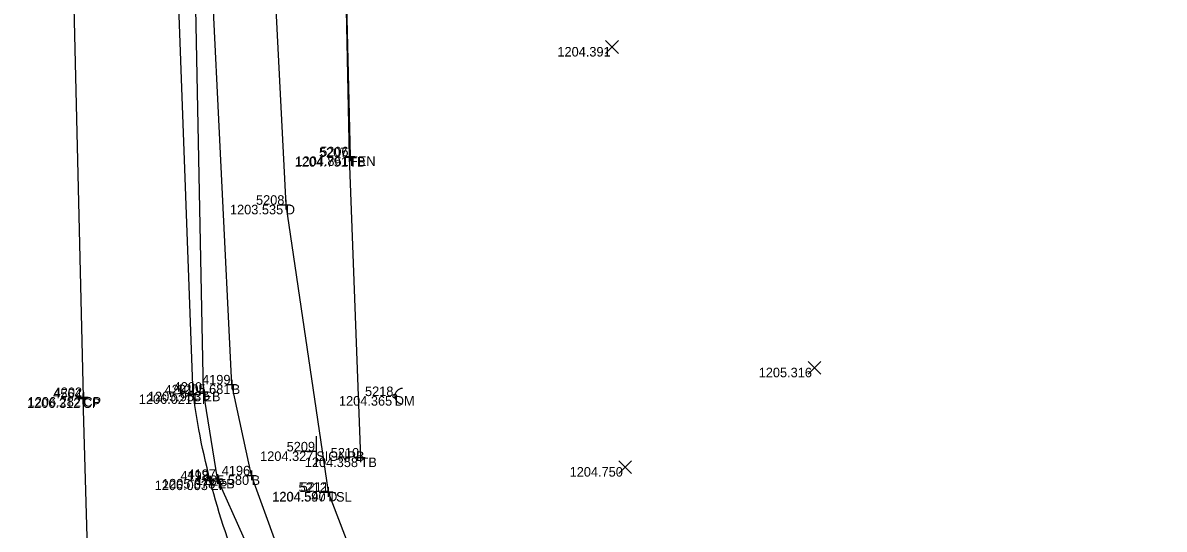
# Model space of a CAD drawing. Extents: x 2044996 to 2050343, y 455232 to 458054.
# Drawn here: x 2047624.3 to 2047743.9, y 457018.9 to 457071.9 of the extents above; entities that cross this region are included whole.
import ezdxf

# ---------------------------------------------------------------- set-up
doc = ezdxf.new("R2010")
doc.units = 0
for name, color, linetype in [('DR_X_Ditch', 7, 'Continuous'), ('DT_X_Contour_Minor', 7, 'Continuous'), ('DT_X_Contour_Text', 7, 'Continuous'), ('DT_X_Island', 7, 'Continuous'), ('DT_X_Spot_Elev', 7, 'Continuous'), ('DT_X_Triangles', 7, 'Continuous'), ('DT_X_Void', 7, 'Continuous'), ('PV_X_COP', 7, 'Continuous'), ('PV_X_EOP', 7, 'Continuous'), ('PV_X_Shoulder_Aggregate', 7, 'Continuous'), ('RD_X_Fence', 7, 'Continuous'), ('SN_X_Public', 7, 'Continuous'), ('SV_X_Break_Lines', 7, 'Continuous'), ('SV_X_Toe_of_Slope', 7, 'Continuous'), ('SV_X_Top_of_Bank', 7, 'Continuous')]:
    doc.layers.add(name, color=color, linetype=linetype)

msp = doc.modelspace()

# ---------------------------------------------------------------- linework, layer by layer
at = {"layer": 'DR_X_Ditch'}
msp.add_lwpolyline([(2047635.93, 457828.45), (2047636.46, 457778.33), (2047635.67, 457731.58), (2047635.87, 457688.92), (2047636.59, 457650.58), (2047637.14, 457615.31), (2047638.36, 457574.87), (2047638.82, 457526.07), (2047639.21, 457482.92), (2047639.9, 457443.66), (2047641.24, 457398.66), (2047642.28, 457344.51), (2047644.03, 457300.89), (2047646.18, 457262.24), (2047646.96, 457237.04), (2047650.76, 457191.22), (2047650.42, 457143.89), (2047649.26, 457104.81), (2047651.9, 457052.9), (2047656.34, 457022.85)], dxfattribs=at)
at = {"layer": 'DT_X_Island'}
msp.add_circle((2047663.32, 457032.87), 0.2, dxfattribs=at)
msp.add_arc((2047664.12, 457032.87), 0.8, 90, 270, dxfattribs=at)
at = {"layer": 'DT_X_Spot_Elev'}
for p, q in [((2047685.41, 457068.75), (2047686.75, 457070.09)), ((2047685.41, 457070.09), (2047686.75, 457068.75)), ((2047706.63, 457035.17), (2047707.96, 457036.5)), ((2047706.63, 457036.5), (2047707.96, 457035.17)), ((2047686.81, 457024.77), (2047688.14, 457026.1)), ((2047686.81, 457026.1), (2047688.14, 457024.77))]:
    msp.add_line(p, q, dxfattribs=at)
at = {"layer": 'DT_X_Void'}
for p, q in [((2047658.54, 457058.39), (2047658.54, 457057.39)), ((2047658.63, 457058.47), (2047658.63, 457057.47)), ((2047658.04, 457057.89), (2047659.04, 457057.89)), ((2047658.13, 457057.97), (2047659.13, 457057.97)), ((2047658.54, 457057.89), (2047658.54, 457057.89)), ((2047658.63, 457057.97), (2047658.63, 457057.97)), ((2047651.9, 457053.4), (2047651.9, 457052.4)), ((2047651.4, 457052.9), (2047652.4, 457052.9)), ((2047651.9, 457052.9), (2047651.9, 457052.9)), ((2047645.73, 457034.09), (2047646.73, 457034.09)), ((2047646.23, 457034.59), (2047646.23, 457033.59)), ((2047646.23, 457034.09), (2047646.23, 457034.09)), ((2047630.62, 457033.13), (2047630.62, 457032.13)), ((2047630.7, 457033.27), (2047630.7, 457032.27)), ((2047641.71, 457033.05), (2047642.71, 457033.05)), ((2047642.21, 457033.55), (2047642.21, 457032.55)), ((2047642.21, 457033.05), (2047642.21, 457033.05)), ((2047642.77, 457033.33), (2047643.77, 457033.33)), ((2047643.27, 457033.83), (2047643.27, 457032.83)), ((2047643.27, 457033.33), (2047643.27, 457033.33)), ((2047630.12, 457032.63), (2047631.12, 457032.63)), ((2047630.2, 457032.77), (2047631.2, 457032.77)), ((2047630.62, 457032.63), (2047630.62, 457032.63)), ((2047630.7, 457032.77), (2047630.7, 457032.77)), ((2047659.73, 457026.94), (2047659.73, 457025.94)), ((2047659.23, 457026.44), (2047660.23, 457026.44)), ((2047659.73, 457026.44), (2047659.73, 457026.44)), ((2047643.98, 457024.53), (2047643.98, 457023.53)), ((2047644.76, 457024.7), (2047644.76, 457023.7)), ((2047647.81, 457024.57), (2047648.81, 457024.57)), ((2047648.31, 457025.07), (2047648.31, 457024.07)), ((2047648.31, 457024.57), (2047648.31, 457024.57)), ((2047643.48, 457024.03), (2047644.48, 457024.03)), ((2047643.98, 457024.03), (2047643.98, 457024.03)), ((2047644.26, 457024.2), (2047645.26, 457024.2)), ((2047644.76, 457024.2), (2047644.76, 457024.2)), ((2047656.34, 457023.35), (2047656.34, 457022.35)), ((2047656.35, 457023.33), (2047656.35, 457022.33)), ((2047655.84, 457022.85), (2047656.84, 457022.85)), ((2047655.85, 457022.83), (2047656.85, 457022.83)), ((2047656.34, 457022.85), (2047656.34, 457022.85)), ((2047656.35, 457022.83), (2047656.35, 457022.83))]:
    msp.add_line(p, q, dxfattribs=at)
at = {"layer": 'PV_X_COP'}
for points in [[(2047630.7, 457032.77), (2047629.57, 457079.46), (2047628.83, 457121.31), (2047627.83, 457168.37), (2047627.23, 457213.89), (2047626.35, 457261.41), (2047625.27, 457313.88), (2047624.14, 457367.69), (2047623.14, 457414.96), (2047622.16, 457463.48), (2047621.21, 457510.6), (2047620.34, 457561.9), (2047619.47, 457614.83), (2047618.33, 457662.23), (2047617.51, 457713.13), (2047616.39, 457759.38), (2047615.44, 457807.27), (2047614.41, 457854.52), (2047614.29, 457881.56), (2047613.16, 457931.14), (2047612.06, 457984.05), (2047611.48, 458032.26), (2047610.91, 458052.26)], [(2047630.62, 457032.63), (2047631.64, 456997.55), (2047632.38, 456961.54), (2047632.83, 456926.92), (2047633.49, 456905.89), (2047634.02, 456875.59), (2047634.74, 456845.71), (2047636.01, 456795.7), (2047636.79, 456753.22), (2047638.14, 456705.84), (2047638.65, 456684.97), (2047639.72, 456638.63)]]:
    msp.add_lwpolyline(points, dxfattribs=at)
at = {"layer": 'PV_X_EOP'}
msp.add_line((2047642.21, 457033.05), (2047640.51, 457078.62), dxfattribs=at)
msp.add_open_spline([(2047683.07, 456986.61), (2047675.94, 456988.74), (2047666.02, 456993.59), (2047654.88, 457002.74), (2047647.77, 457012.14), (2047644.12, 457022.51), (2047642.59, 457029.98), (2047642.21, 457033.05)], degree=3, dxfattribs=at)
at = {"layer": 'PV_X_Shoulder_Aggregate'}
msp.add_lwpolyline([(2047765.41, 456957.6), (2047718.77, 456974.89), (2047683.47, 456987.55), (2047664.01, 456996.43), (2047655.41, 457004.2), (2047650.14, 457012.19), (2047644.76, 457024.2), (2047643.27, 457033.33), (2047642.36, 457078.68), (2047641.18, 457122.01), (2047640.21, 457169.15), (2047639.13, 457212.34), (2047637.97, 457261.48), (2047636.93, 457312.89), (2047635.93, 457367.47)], dxfattribs=at)
at = {"layer": 'RD_X_Fence'}
msp.add_lwpolyline([(2047648.14, 457619.76), (2047649.39, 457574.65), (2047649.98, 457529.13), (2047650.66, 457480.39), (2047651.7, 457447.16), (2047652.23, 457398.03), (2047653.85, 457346.51), (2047654.21, 457298.97), (2047654.82, 457261.49), (2047656.66, 457189.93), (2047656.98, 457146.63), (2047657.53, 457104.26), (2047658.63, 457057.97)], dxfattribs=at)
at = {"layer": 'SN_X_Public'}
for p, q in [((2047655.09, 457028.68), (2047655.09, 457025.48)), ((2047655.09, 457027.08), (2047653.49, 457027.08))]:
    msp.add_line(p, q, dxfattribs=at)
at = {"layer": 'SV_X_Break_Lines'}
msp.add_lwpolyline([(2047766.63, 456959.74), (2047718.99, 456976.33), (2047684.01, 456989.24), (2047664.81, 456998.06), (2047657.38, 457005.81), (2047652.26, 457013.72), (2047648.31, 457024.57), (2047646.23, 457034.09), (2047644.07, 457078.24), (2047642.74, 457121.94), (2047641.84, 457169.12), (2047640.7, 457212.33), (2047639.26, 457261.64), (2047638.13, 457312.9), (2047637.8, 457367.1)], dxfattribs=at)
at = {"layer": 'SV_X_Toe_of_Slope'}
msp.add_lwpolyline([(2047656.35, 457022.83), (2047660.05, 457013.16), (2047664.41, 457005.04), (2047675.76, 456997.03), (2047717.96, 456981.3), (2047760.28, 456966.23)], dxfattribs=at)
at = {"layer": 'SV_X_Top_of_Bank'}
msp.add_lwpolyline([(2047640.57, 457829.63), (2047642.73, 457776.65), (2047644.22, 457735.31), (2047644.62, 457692.67), (2047644.93, 457653.27), (2047648.25, 457619.87), (2047649.32, 457574.48), (2047650.08, 457529.2), (2047650.6, 457480.31), (2047651.65, 457447.12), (2047652.29, 457398.02), (2047653.83, 457346.33), (2047654.34, 457298.99), (2047654.68, 457261.41), (2047656.79, 457189.89), (2047656.98, 457146.62), (2047657.59, 457104.22), (2047658.54, 457057.89), (2047659.73, 457026.44)], dxfattribs=at)

# ---------------------------------------------------------------- texts
at = {"layer": 'DT_X_Contour_Minor'}
for s, p in [('1204.391', (2047680.36, 457068.42)), ('1204.791', (2047652.83, 457056.89)), ('1204.861', (2047652.91, 457056.97)), ('1203.535', (2047646.05, 457051.9)), ('1205.316', (2047701.45, 457034.84)), ('1205.681', (2047640.52, 457033.09)), ('1206.021', (2047636.5, 457032.05)), ('1205.953', (2047637.45, 457032.33)), ('1206.312', (2047624.79, 457031.63)), ('1206.282', (2047624.86, 457031.77)), ('1204.365', (2047657.47, 457031.87)), ('1204.327', (2047649.21, 457026.08)), ('1204.358', (2047653.89, 457025.44)), ('1205.580', (2047642.48, 457023.57)), ('1204.750', (2047681.64, 457024.44)), ('1206.003', (2047638.16, 457023.03)), ('1205.878', (2047638.93, 457023.2)), ('1204.597', (2047650.47, 457021.83)), ('1204.540', (2047650.5, 457021.85))]:
    msp.add_text(s, height=1, dxfattribs=at).set_placement(p)
at = {"layer": 'DT_X_Contour_Text'}
for s, p in [('TB', (2047658.54, 457056.89)), ('FEN', (2047658.63, 457056.97)), ('D', (2047651.9, 457051.9)), ('B', (2047646.23, 457033.09)), ('EP', (2047642.21, 457032.05)), ('EB', (2047643.27, 457032.33)), ('CP', (2047630.62, 457031.63)), ('CP', (2047630.7, 457031.77)), ('DM', (2047663.32, 457031.87)), ('SIGNPB', (2047655.09, 457026.08)), ('TB', (2047659.73, 457025.44)), ('B', (2047648.31, 457023.57)), ('EP', (2047643.98, 457023.03)), ('EB', (2047644.76, 457023.2)), ('TSL', (2047656.35, 457021.83)), ('D', (2047656.34, 457021.85))]:
    msp.add_text(s, height=1, dxfattribs=at).set_placement(p)
at = {"layer": 'DT_X_Triangles'}
for s, p in [('5207', (2047655.38, 457057.89)), ('5206', (2047655.5, 457057.97)), ('5208', (2047648.78, 457052.9)), ('4200', (2047640.15, 457033.33)), ('4199', (2047643.13, 457034.09)), ('4564', (2047627.53, 457032.63)), ('4202', (2047627.58, 457032.77)), ('4201', (2047639.21, 457033.05)), ('5218', (2047660.2, 457032.87)), ('5209', (2047651.99, 457027.08)), ('5210', (2047656.61, 457026.44)), ('4198', (2047640.86, 457024.03)), ('4197', (2047641.6, 457024.2)), ('4196', (2047645.19, 457024.57)), ('5212', (2047653.24, 457022.83)), ('5211', (2047653.44, 457022.85))]:
    msp.add_text(s, height=1, dxfattribs=at).set_placement(p)

doc.saveas('drawing.dxf')
